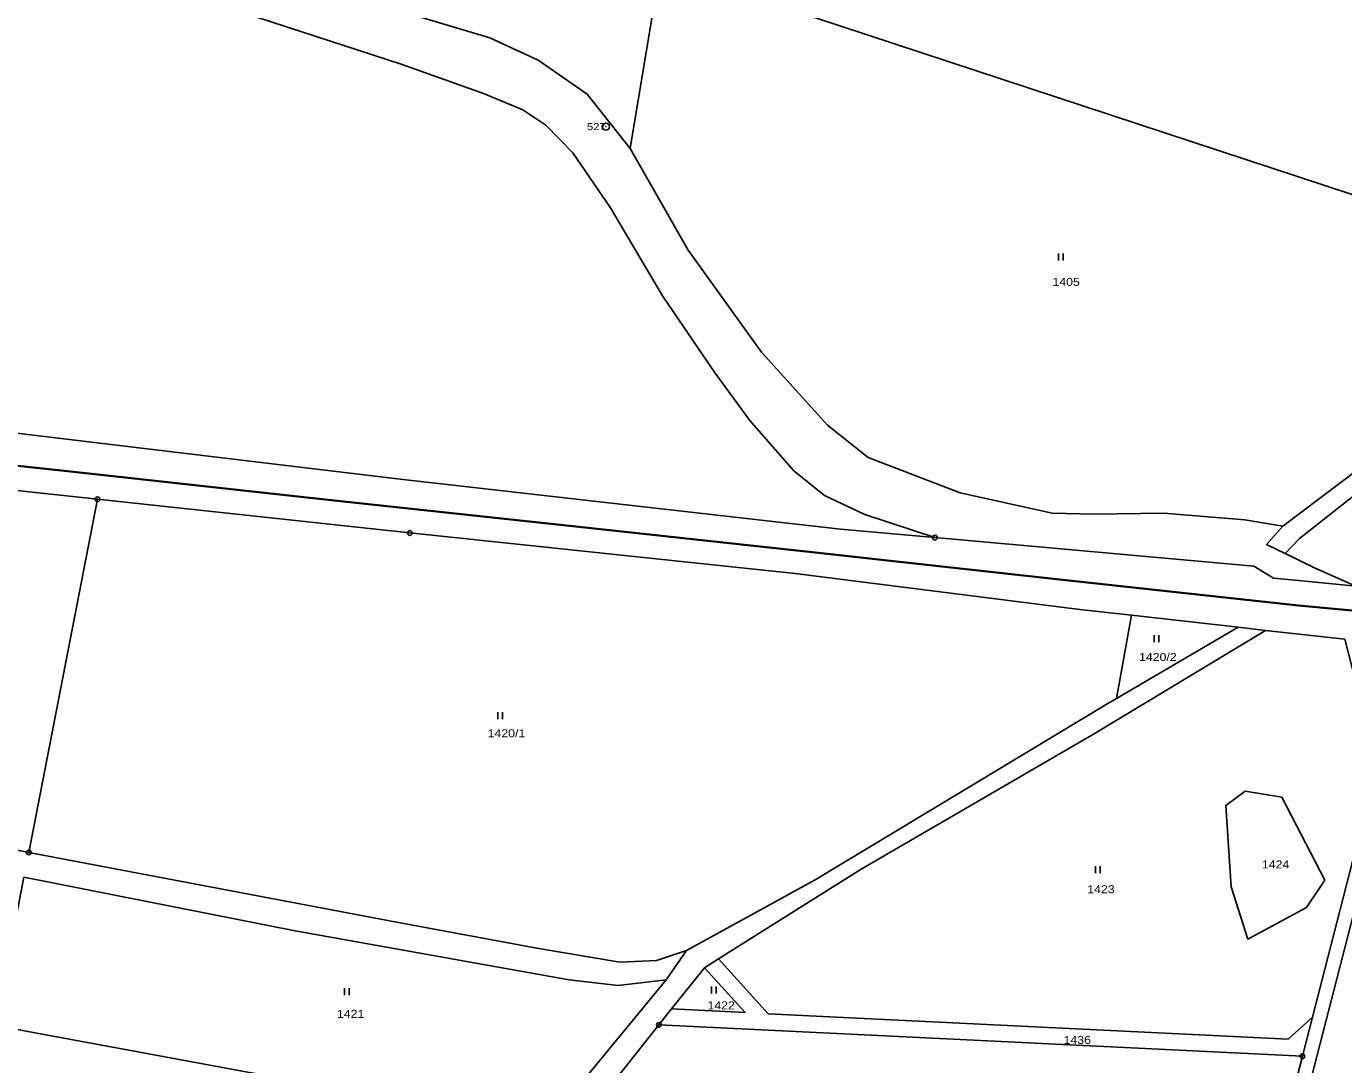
# Model space of a CAD drawing. Extents: x -872229 to -869198, y -1075981 to -1074329.
# Drawn here: x -870769 to -870489.1, y -1075586.7 to -1075366 of the extents above; entities that cross this region are included whole.
import ezdxf
from ezdxf.enums import TextEntityAlignment as Align

# ---------------------------------------------------------------- set-up
doc = ezdxf.new("R2010")
doc.units = 0
doc.header["$LTSCALE"] = 0.68
for name, color, linetype, lineweight in [('1', 7, 'Continuous', 25), ('3', 7, 'Continuous', 25), ('6', 7, 'Continuous', 25), ('8', 7, 'Continuous', 25)]:
    doc.layers.add(name, color=color, linetype=linetype, lineweight=lineweight)
doc.layers.add('2', color=7, linetype='Continuous')

msp = doc.modelspace()

# ---------------------------------------------------------------- linework, layer by layer
at = {"layer": '1'}
for p, q in [((-870537.38, -1075508.91), (-870534.21, -1075491.19)), ((-870511.55, -1075493.74), (-870534.21, -1075491.19)), ((-870621.92, -1075564.22), (-870624.93, -1075566.11)), ((-870624.93, -1075566.11), (-870631.89, -1075574.87)), ((-870631.89, -1075574.87), (-870634.57, -1075578.24)), ((-870495.74, -1075576.59), (-870497.88, -1075584.92)), ((-870497.88, -1075584.92), (-870634.57, -1075578.24))]:
    msp.add_line(p, q, dxfattribs=at)
for points in [[(-870764.18, -1075335.84), (-870757.26, -1075338.7), (-870738.34, -1075346.2), (-870695.93, -1075360.93), (-870670.53, -1075368.46), (-870660.23, -1075373.2), (-870649.84, -1075380.47), (-870640.68, -1075391.97)], [(-870805.1, -1075337.55), (-870790.85, -1075341.74), (-870773.54, -1075347.26), (-870743.94, -1075356.68), (-870719.6, -1075364.23), (-870689.31, -1075374.07), (-870671.81, -1075380.32), (-870663.52, -1075383.76), (-870658.58, -1075387.02), (-870652.84, -1075392.9), (-870644.86, -1075404.62), (-870633.82, -1075423.29), (-870622.61, -1075439.76), (-870615.24, -1075449.79), (-870605.9, -1075460.53), (-870599.41, -1075465.72), (-870590.82, -1075469.8), (-870575.95, -1075474.7)], [(-870435.43, -1075418.82), (-870618.95, -1075358.37), (-870635.72, -1075362.14), (-870640.68, -1075391.97)], [(-870640.68, -1075391.97), (-870628.39, -1075413.58), (-870612.82, -1075435.28), (-870598.75, -1075450.8), (-870590.13, -1075457.68), (-870570.55, -1075465.2), (-870551.03, -1075469.53), (-870542.08, -1075469.72), (-870527.36, -1075469.51), (-870510.1, -1075470.94), (-870502.02, -1075472.23)], [(-870435.43, -1075418.82), (-870439.55, -1075423.36), (-870447.86, -1075430.89), (-870470, -1075448.07), (-870502.02, -1075472.23)], [(-870501.5, -1075478.06), (-870498.51, -1075474.88), (-870484.83, -1075464.11), (-870464.21, -1075448.97), (-870443.12, -1075433.33), (-870432.04, -1075422.14), (-870430.66, -1075420.4)], [(-870949.31, -1075435.5), (-870912.76, -1075439.69), (-870824.05, -1075448.17), (-870816.69, -1075448.69), (-870813.04, -1075448.95), (-870783.54, -1075451.03), (-870689.55, -1075462.28), (-870596.02, -1075472.9), (-870575.95, -1075474.7)], [(-870753.84, -1075466.53), (-870783.62, -1075463.3), (-870803.76, -1075465.35), (-870814.2, -1075463.42), (-870817.87, -1075462.75)], [(-870825.33, -1075530.87), (-870819.8, -1075531.88), (-870773.33, -1075540.65), (-870768.45, -1075541.58), (-870753.84, -1075466.53)], [(-870534.21, -1075491.19), (-870545.14, -1075489.96), (-870605.6, -1075482.35), (-870687.49, -1075473.71), (-870753.84, -1075466.53)], [(-870502.02, -1075472.23), (-870505.5, -1075476.14), (-870501.5, -1075478.06)], [(-870575.95, -1075474.7), (-870508.22, -1075480.79), (-870504.01, -1075483.3), (-870498.65, -1075483.83), (-870486.5, -1075484.99)], [(-870486.5, -1075484.99), (-870495.19, -1075481.2), (-870501.5, -1075478.06)], [(-870505.74, -1075494.4), (-870542.26, -1075516.43), (-870591.61, -1075545.13), (-870600.16, -1075550.52), (-870621.92, -1075564.22)], [(-870505.74, -1075494.4), (-870511.55, -1075493.74), (-870537.38, -1075508.91)], [(-870495.74, -1075576.59), (-870481.98, -1075523.1), (-870488.89, -1075496.3), (-870505.74, -1075494.4)], [(-870537.38, -1075508.91), (-870539.21, -1075509.98), (-870601.38, -1075547.4), (-870628.73, -1075562.46), (-870633.02, -1075568.68)], [(-870557.85, -1075746.37), (-870540.19, -1075739.3), (-870505.25, -1075704.66), (-870498.26, -1075598.45), (-870480.43, -1075529.12)], [(-870628.73, -1075562.46), (-870635.06, -1075564.59), (-870642.9, -1075564.91), (-870660.48, -1075561.95), (-870690.68, -1075556.37), (-870768.45, -1075541.58)], [(-870769.48, -1075546.88), (-870775.56, -1075578.36), (-870723.44, -1075587.98), (-870658.76, -1075599.92), (-870633.02, -1075568.68)], [(-870633.02, -1075568.68), (-870643.23, -1075569.87), (-870653.67, -1075568.67), (-870711.88, -1075558.28), (-870769.48, -1075546.88)], [(-870621.92, -1075564.22), (-870611.35, -1075575.87), (-870500.89, -1075581.27), (-870495.74, -1075576.59)], [(-870631.89, -1075574.87), (-870616.29, -1075575.63), (-870624.93, -1075566.11)], [(-870634.57, -1075578.24), (-870644.53, -1075590.75), (-870653.4, -1075603.02), (-870665.74, -1075618.29), (-870675.84, -1075631.34), (-870683.76, -1075646.76), (-870687.46, -1075663.9), (-870691.39, -1075690.84), (-870699.49, -1075756.36), (-870703.4, -1075769.57), (-870685.61, -1075768.87), (-870662.6, -1075767.96)], [(-870497.88, -1075584.92), (-870501.24, -1075597.99), (-870508.17, -1075703.33), (-870541.87, -1075736.74), (-870558.64, -1075743.46), (-870618.91, -1075752.53), (-870631.08, -1075751.8), (-870646.39, -1075758.16), (-870662.6, -1075767.96)]]:
    msp.add_lwpolyline(points, dxfattribs=at)
msp.add_lwpolyline([(-870502.27, -1075529.87), (-870493.12, -1075547.49), (-870497.02, -1075553.32), (-870509.45, -1075560.02), (-870513.03, -1075548.94), (-870514.12, -1075531.6), (-870510.05, -1075528.58)], close=True, dxfattribs=at)
at = {"layer": '3'}
for p, q in [((-870549.691, -1075415.82), (-870549.691, -1075414.32)), ((-870548.69, -1075415.82), (-870548.69, -1075414.32)), ((-870529.381, -1075496.9), (-870529.381, -1075495.4)), ((-870528.38, -1075496.9), (-870528.38, -1075495.4)), ((-870668.781, -1075513.28), (-870668.781, -1075511.78)), ((-870667.78, -1075513.28), (-870667.78, -1075511.78)), ((-870541.831, -1075546), (-870541.831, -1075544.5)), ((-870540.83, -1075546), (-870540.83, -1075544.5)), ((-870701.391, -1075571.92), (-870701.391, -1075570.42)), ((-870700.39, -1075571.92), (-870700.39, -1075570.42)), ((-870623.411, -1075571.57), (-870623.411, -1075570.07)), ((-870622.41, -1075571.57), (-870622.41, -1075570.07))]:
    msp.add_line(p, q, dxfattribs=at)
at = {"layer": '6', "lineweight": 35}
for p, q in [((-870759.62, -1075460.64), (-870704.19, -1075466.72)), ((-870602.02, -1075477.76), (-870551.39, -1075483.38))]:
    msp.add_line(p, q, dxfattribs=at)
for points in [[(-870865.22, -1075449.1), (-870815.6, -1075454.63), (-870759.62, -1075460.64)], [(-870704.19, -1075466.72), (-870652.21, -1075472.36), (-870602.02, -1075477.76)], [(-870551.39, -1075483.38), (-870498.7, -1075489.12), (-870466.81, -1075492.11)]]:
    msp.add_lwpolyline(points, dxfattribs=at)
at = {"layer": '8'}
for centre, radius in [((-870645.85, -1075387.3498), 0.75), ((-870645.85, -1075387.3498), 0.03), ((-870753.84, -1075466.5299), 0.5), ((-870753.84, -1075466.5299), 0.0303), ((-870687.49, -1075473.7099), 0.5), ((-870687.49, -1075473.7099), 0.0303), ((-870575.95, -1075474.6999), 0.5), ((-870575.95, -1075474.6999), 0.0303), ((-870768.45, -1075541.5799), 0.5), ((-870768.45, -1075541.5799), 0.0303), ((-870634.57, -1075578.2399), 0.5), ((-870634.57, -1075578.2399), 0.0303), ((-870497.88, -1075584.9199), 0.5), ((-870497.88, -1075584.9199), 0.0303)]:
    msp.add_circle(centre, radius, dxfattribs=at)

# ---------------------------------------------------------------- texts
at = {"layer": '2', "width": 1.15}
for s, p in [('1405', (-870550.97, -1075421.19)), ('1420/2', (-870532.58, -1075500.91)), ('1420/1', (-870670.97, -1075517.12)), ('1424', (-870506.48, -1075544.99)), ('1423', (-870543.58, -1075550.26)), ('1422', (-870624.27, -1075574.95)), ('1421', (-870702.98, -1075576.75)), ('1436', (-870548.61, -1075582.28))]:
    msp.add_text(s, height=1.7, dxfattribs=at).set_placement(p)
at = {"layer": '8', "width": 1.2}
msp.add_text('527', height=1.5, dxfattribs=at).set_placement((-870645.85, -1075388.1), align=Align.RIGHT)

doc.saveas('drawing.dxf')
